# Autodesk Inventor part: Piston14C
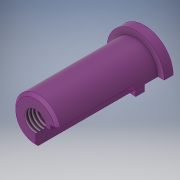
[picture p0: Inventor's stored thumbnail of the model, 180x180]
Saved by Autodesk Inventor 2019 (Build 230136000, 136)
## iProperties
Created: 2019-02
Part Number: Piston14C
Material: Générique
Document SubType Name: Modeling
Designer: si-nd67
Density: 1 g/cm^3
Appearance: Lisse - Violet
Mass: 21.5536 g
Surface Area: 91.2049 cm^2
Volume: 21.5536 cm^3
Author: si-nd67
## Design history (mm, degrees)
sketch "Esquisse1"
  geometry: L1 (0, 27.984)-(12.5, 27.984); L2 (12.5, 27.984)-(12.5, -28.016); L3 (12.5, -28.016)-(16, -28.016); L4 (16, -28.016)-(16, -33.016); L5 (16, -33.016)-(0, -33.016); L6 (0, -33.016)-(0, 27.984); 1 further point
  constraints: 12 end point, 5 perpendicular, 1 horizontal
  dimensions: "d0" = 25 diameter of L2 L6; "d1" = 5 distance of L3.end L4.end; "d2" = 32 diameter of L4 L6; "d3" = 56 distance of L1.end L2.end
revolve "Révolution1" sketch "Esquisse1" stored, may be unused: angle "d4" = 90 deg
sketch "Esquisse2"
  geometry: C1 r 7.5 at (0, 0); 1 further point
  constraints: 1 centre point, 1 coincident
  dimensions: "d5" = 15 diameter of C1
extrude "Extrusion1" cut sketch "Esquisse2" distance "d6" = 36; taper "d7" = 0 deg
sketch "Esquisse3"
  geometry: 2 further points
  constraints: 1 coincident
hole "Perçage1" sketch "Esquisse3" at (0, 0) diameter "d8" = 11.835; stored, may be unused: countersink angle "d12" = 90 deg, drill point angle "d14" = 0 deg; dims "d9" = 25, "d10" = 4, "d11" = 2, "d13" = 25
sketch "Esquisse5"
  geometry: L1 (-8.5, 52.101)-(-8.5, -3.016); L2 (-12.5, 27.984)-(12.5, 27.984) reference; L3 (-48.5, -3.016)-(-48.5, 52.101); L4 (-8.5, 52.101)-(-48.5, 52.101); A1 r 20 centre (-28.5, -3.016) between (-48.5, -3.016) and (-8.5, -3.016); 1 further point
  constraints: 6 end point, 2 point on circle, 2 tangent, 2 vertical, 1 centre point, 1 horizontal
  dimensions: "d15" = 40 diameter of A1; "d16" = 31 distance from line of A1.centre L2; "d17" = 8.5 distance from line of L1 point (0, 0); "d18" = 55.11758 distance of L3.start L3.end
extrude "Extrusion2" cut sketch "Esquisse5" stored distance "d19" = 5; taper "d20" = 0 deg
chamfer "Chanfrein1" distance "d21" = 1.5; stored, may be unused: second distance "d22" = 2, angle "d23" = 45 deg
sketch "Esquisse8"
  geometry: L1 (-8.5, 2.5)-(14.095, 2.5); L2 (14.095, 2.5)-(14.095, -16.852); L3 (14.095, -16.852)-(-8.5, -16.852); L4 (-8.5, -16.852)-(-8.5, 2.5)
  constraints: 8 end point, 2 parallel, 1 horizontal, 1 perpendicular
extrude "Extrusion5" cut sketch "Esquisse8" extent not by distance; stored distance "d28" = 10; taper "d29" = 0 deg
node "Solide1"
